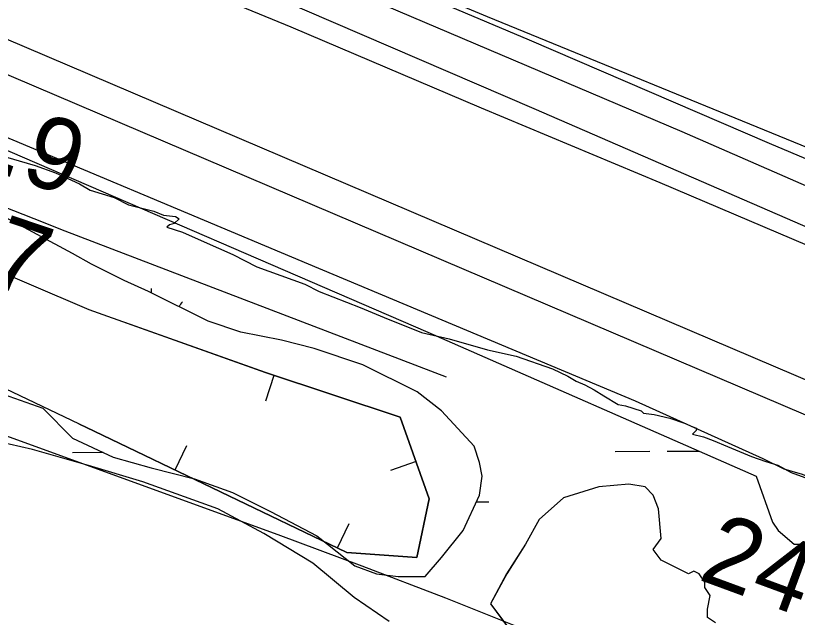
# Model space of a CAD drawing. Extents: x 3329297 to 3367176, y 649250 to 674653.
# Drawn here: x 3337023 to 3337745, y 671007 to 671563 of the extents above; entities that cross this region are included whole.
import ezdxf

# ---------------------------------------------------------------- set-up
doc = ezdxf.new("R2010")
doc.units = 0
for name, color, linetype in [('V-BORW-LINE', 7, 'Continuous'), ('V-LEVE-TOET', 7, 'Continuous'), ('V-RIVR-EDGE', 7, 'Continuous'), ('V-RIVR-RANG', 7, 'Continuous'), ('V-ROAD-CNTR', 7, 'Continuous'), ('V-SITE-VEGE', 7, 'Continuous'), ('V-SURV-LINE', 7, 'Continuous'), ('V-TOPO-MAJR', 7, 'Continuous'), ('V-TOPO-SHOR', 7, 'Continuous'), ('V-WETL-SWMP', 7, 'Continuous')]:
    doc.layers.add(name, color=color, linetype=linetype)

msp = doc.modelspace()

# ---------------------------------------------------------------- linework, layer by layer
at = {"layer": 'V-BORW-LINE'}
for p, q in [((3337261.34, 671230.61), (3337253.51, 671206.87)), ((3337169.91, 671143.17), (3337180.72, 671165.71)), ((3337392.71, 671150.96), (3337369.16, 671142.59)), ((3337320.11, 671071.1), (3337330.93, 671093.64))]:
    msp.add_line(p, q, dxfattribs=at)
for points in [[(3336137.13, 671704.9), (3336329.71, 671609.64), (3336446.55, 671579.02), (3336516.76, 671528.05), (3336660.06, 671480.86), (3336870.09, 671385.28), (3337090.13, 671291.42), (3337253.57, 671233.18), (3337378.09, 671192.1), (3337404.91, 671116.64), (3337393.5, 671062.16), (3337328.83, 671066.91), (3337095.24, 671179), (3336875.94, 671283.56), (3336663.33, 671355.4), (3336502.56, 671407.46), (3336272.56, 671492.78), (3336062.54, 671602.07)], [(3337080.86, 671185.86), (3337095.24, 671179), (3337328.83, 671066.91), (3337393.5, 671062.16), (3337404.91, 671116.64), (3337378.09, 671192.1), (3337253.57, 671233.18), (3337123.46, 671279.54)]]:
    msp.add_lwpolyline(points, dxfattribs=at)
at = {"layer": 'V-LEVE-TOET'}
for points in [[(3335803.12, 672183.55), (3335980.51, 672109.48), (3336073.36, 672067.84), (3336217.76, 672005.99), (3336352.53, 671946.93), (3336517.19, 671873.95), (3336710.98, 671786.23), (3336942.43, 671688.86), (3337134.25, 671611.38), (3337276.94, 671552.63), (3337452.78, 671477.7), (3337618.08, 671408.71), (3337810.05, 671327.27)], [(3340086.07, 669878.32), (3339928.04, 670005.5), (3339884.34, 670048.24), (3339817.4, 670097.22), (3339686.01, 670171.48), (3339507.75, 670267.73), (3339342.66, 670351.8), (3339186.35, 670434.62), (3338995.14, 670537.52), (3338794.67, 670646.24), (3338482.64, 670816.66), (3338239.58, 670927.07), (3338016.97, 671021.61), (3337749.83, 671139.03), (3337732.98, 671143.93), (3337713.57, 671153.49), (3337595.68, 671206.86), (3337293.29, 671333.23), (3336964.27, 671471.26), (3336549.79, 671644.86), (3336202.79, 671796.48), (3335798.63, 671978.49)]]:
    msp.add_lwpolyline(points, dxfattribs=at)
at = {"layer": 'V-RIVR-EDGE'}
msp.add_spline([(3339166.35, 669632.45), (3339148.52, 669636.37), (3339138.83, 669636.78), (3339122.94, 669641.48), (3339105.12, 669646.95), (3339096.99, 669652.01), (3339093.12, 669656.29), (3339089.26, 669664.44), (3339086.56, 669669.1), (3339078.82, 669674.94), (3339053.64, 669688.18), (3339028.47, 669702.21), (3339020.72, 669706.49), (3339018, 669704.17), (3339012.57, 669704.57), (3339008.7, 669708.07), (3339008.32, 669710.4), (3339007.94, 669713.12), (3339007.56, 669715.06), (3338988.58, 669723.63), (3338974.64, 669732.59), (3338973.09, 669734.53), (3338972.71, 669738.02), (3338974.27, 669740.35), (3338974.28, 669743.84), (3338966.94, 669753.94), (3338965.01, 669758.6), (3338963.85, 669760.54), (3338956.49, 669764.43), (3338944.87, 669769.5), (3338928.21, 669778.08), (3338920.86, 669785.07), (3338906.56, 669803.34), (3338897.28, 669814.22), (3338888, 669824.71), (3338880.26, 669833.26), (3338874.07, 669838.71), (3338867.87, 669840.27), (3338862.06, 669843), (3338858.57, 669843.01), (3338858.58, 669844.95), (3338858.24, 669867.83), (3338860.58, 669870.93), (3338861.75, 669873.25), (3338861.76, 669876.35), (3338860.21, 669879.46), (3338854.02, 669882.58), (3338849.02, 669903.14), (3338843.63, 669917.51), (3338832.81, 669931.11), (3338822.75, 669940.83), (3338804.56, 669955.22), (3338800.68, 669956.78), (3338796.03, 669956.79), (3338788.66, 669955.26), (3338782.44, 669952.17), (3338775.47, 669955.68), (3338770.44, 669960.35), (3338765.41, 669965.01), (3338754.18, 669972.41), (3338742.57, 669981.36), (3338728.24, 669988.76), (3338714.68, 669995), (3338701.13, 670003.56), (3338693.4, 670012.11), (3338687.99, 670020.27), (3338682.59, 670033.47), (3338677.18, 670040.46), (3338665.17, 670046.31), (3338655.1, 670048.66), (3338655.48, 670045.95), (3338653.54, 670045.56), (3338643.46, 670046.36), (3338635.32, 670050.26), (3338633, 670052.98), (3338626.41, 670055.33), (3338615.17, 670057.29), (3338608.97, 670058.08), (3338601.61, 670062.76), (3338592.32, 670069.37), (3338582.25, 670071.72), (3338574.11, 670074.46), (3338568.3, 670078.74), (3338562.5, 670084.57), (3338561.34, 670087.67), (3338554.75, 670088.85), (3338551.26, 670089.25), (3338548.94, 670091.97), (3338544.31, 670098.58), (3338517.19, 670108.73), (3338513.32, 670111.84), (3338511.39, 670115.72), (3338497.82, 670118.86), (3338480, 670125.88), (3338471.48, 670130.17), (3338466.45, 670134.83), (3338451.73, 670140.3), (3338441.26, 670142.65), (3338438.16, 670142.27), (3338431.18, 670145.39), (3338420.34, 670150.07), (3338407.93, 670152.43), (3338393.21, 670156.73), (3338378.49, 670165.69), (3338345.2, 670189.43), (3338316.55, 670206.56), (3338280.93, 670231.47), (3338237.55, 670254.45), (3338210.45, 670270.81), (3338182.57, 670289.88), (3338148.9, 670317.5), (3338126.07, 670336.94), (3338116.01, 670348.22), (3338106.73, 670356.77), (3338093.56, 670363.78), (3338076.9, 670368.87), (3338057.53, 670376.28), (3338042.81, 670383.3), (3338026.54, 670392.65), (3338007.18, 670402.39), (3337994, 670405.52), (3337971.52, 670413.34), (3337948.66, 670420.76), (3337916.51, 670434.03), (3337912.65, 670440.63), (3337911.11, 670448.78), (3337908.8, 670453.82), (3337904.54, 670455.77), (3337890.98, 670459.68), (3337883.62, 670464.74), (3337879.36, 670466.69), (3337872.38, 670467.1), (3337862.68, 670467.12), (3337849.88, 670465.99), (3337839.8, 670463.69), (3337826.22, 670462.56), (3337810.72, 670465.7), (3337802.19, 670469.21), (3337788.25, 670478.16), (3337779.73, 670480.51), (3337774.3, 670481.69), (3337768.89, 670486.74), (3337764.63, 670490.63), (3337755.72, 670494.92), (3337749.13, 670496.88), (3337745.26, 670497.27), (3337740.6, 670495.35), (3337738.66, 670496.13), (3337735.18, 670499.24), (3337729.76, 670503.52), (3337724.73, 670508.18), (3337720.08, 670512.07), (3337706.13, 670514.43), (3337677.86, 670531.18), (3337643.77, 670545.22), (3337600.78, 670567.05), (3337560.1, 670585.37), (3337510.14, 670611.87), (3337463.28, 670636.42), (3337442.36, 670644.22), (3337416.78, 670652.43), (3337405.55, 670657.5), (3337401.68, 670661.39), (3337400.13, 670663.33), (3337395.49, 670665.67), (3337388.89, 670666.07), (3337376.88, 670670.76), (3337362.94, 670677.77), (3337340.87, 670690.62), (3337309.5, 670706.99), (3337291.29, 670714.79), (3337276.18, 670722.97), (3337252.56, 670736.99), (3337220.04, 670756.85), (3337154.99, 670798.5), (3337124.41, 670821.07), (3337111.24, 670827.31), (3337094.19, 670832.78), (3337075.97, 670836.7), (3337050.39, 670842.59), (3337028.69, 670849.62), (3337007.78, 670860.53), (3336991.89, 670867.94), (3336983.37, 670871.06), (3336969.03, 670873.42), (3336939.95, 670875.43), (3336901.97, 670884.45), (3336863.6, 670895.79), (3336821.37, 670910.63), (3336786.5, 670926.23), (3336740.02, 670949.61), (3336682.31, 670976.12), (3336635.44, 670997.18), (3336603.68, 671013.55), (3336585.47, 671022.51), (3336583.15, 671026.4), (3336580.06, 671031.06), (3336576.19, 671034.56), (3336549.46, 671045.09), (3336500.24, 671058.01), (3336451.41, 671070.16), (3336425.44, 671074.49), (3336399.85, 671076.49), (3336361.07, 671078.91), (3336337.43, 671082.85), (3336313.4, 671088.34), (3336290.92, 671094.6), (3336280.46, 671097.34), (3336275.41, 671097.35), (3336257.58, 671097.39), (3336194.82, 671123.92), (3336129.35, 671154.33), (3336078.61, 671179.66), (3336032.91, 671203.04), (3335979.46, 671230.32), (3335943.05, 671245.54), (3335907.79, 671259.2), (3335894.23, 671264.66), (3335887.64, 671265.45), (3335873.31, 671273.63), (3335871.38, 671277.13), (3335862.86, 671281.41), (3335831.09, 671293.51), (3335799.33, 671308.72), (3335763.7, 671327.42), (3335724.58, 671346.9), (3335714.51, 671351.97), (3335703.27, 671355.1), (3335699.01, 671358.21), (3335680.04, 671369.9), (3335645.95, 671385.49), (3335603.71, 671399.17), (3335573.09, 671406.61), (3335518.06, 671419.93), (3335470.4, 671436.73), (3335433.98, 671449.62), (3335405.32, 671465.97), (3335397.96, 671471.03), (3335385.94, 671471.06), (3335366.94, 671468.78), (3335345.98, 671463.02), (3335338.62, 671464.59), (3335338.62, 671467.3), (3335339.03, 671475.83), (3335337.87, 671478.94), (3335334.39, 671482.05), (3335319.67, 671486.74), (3335303, 671491.05), (3335280.12, 671488.39), (3335259.15, 671479.52), (3335245.56, 671472.19), (3335233.15, 671471.44), (3335223.85, 671474.18), (3335210.68, 671481.97), (3335198.67, 671485.88), (3335156.4, 671487.53), (3335124.61, 671488.39), (3335114.13, 671484.92), (3335094.71, 671474.11), (3335085.4, 671473.36), (3335075.32, 671475.71), (3335065.63, 671477.67), (3335064.86, 671478.45), (3335067.59, 671483.1), (3335066.81, 671484.65), (3335063.72, 671489.31), (3335039.71, 671501.39), (3335020.73, 671509.2), (3335003.28, 671511.95), (3334994.76, 671515.46), (3334990.89, 671517.03), (3334963, 671533.38), (3334933.18, 671549.36), (3334916.12, 671551.34), (3334894.42, 671557.6), (3334863.43, 671571.25), (3334847.95, 671581.75), (3334834.78, 671587.99), (3334809.21, 671598.53), (3334767.76, 671617.24), (3334744.9, 671627.77), (3334711.2, 671642.2), (3334691.44, 671649.23), (3334670.12, 671653.16), (3334647.65, 671659.81), (3334620.14, 671672.29), (3334605.42, 671678.53), (3334581, 671683.24), (3334555.81, 671689.12), (3334542.23, 671688.38), (3334534.09, 671688.79), (3334531.39, 671696.55), (3334523.66, 671706.27), (3334505.85, 671714.84), (3334480.26, 671719.17), (3334460.49, 671721.93), (3334457, 671720.39), (3334455.05, 671716.91), (3334456.59, 671713.8), (3334463.19, 671714.56), (3334467.45, 671712.22), (3334467.44, 671710.28), (3334462.78, 671708.35), (3334446.88, 671706.84), (3334429.04, 671707.66), (3334403.46, 671713.93), (3334397.66, 671718.6), (3334391.46, 671722.88), (3334378.67, 671723.69), (3334340.28, 671727.27), (3334305.39, 671730.07), (3334290.26, 671730.11), (3334281.35, 671731.68), (3334271.66, 671734.81), (3334266.23, 671735.6), (3334258.08, 671732.9), (3334246.43, 671726.73), (3334241.39, 671726.35), (3334232.48, 671729.48), (3334218.91, 671729.9), (3334190.6, 671730.74), (3334178.97, 671731.94), (3334163.47, 671737.4), (3334156.1, 671736.65), (3334151.44, 671732.39), (3334148.33, 671732.4), (3334142.53, 671735.91), (3334132.83, 671736.32), (3334110.73, 671737.53), (3334106.86, 671739.48), (3334099.89, 671744.15), (3334081.28, 671748.08), (3334072.75, 671747.71), (3334041.74, 671753.61), (3334018.09, 671757.54), (3334010.35, 671760.28), (3333999.89, 671767.67), (3333992.15, 671771.95), (3333987.1, 671771.19), (3333984.38, 671768.48), (3333980.12, 671768.49), (3333976.64, 671772.77), (3333969.66, 671775.11), (3333958.81, 671778.24), (3333949.91, 671783.31), (3333945.64, 671782.93), (3333941.37, 671782.16), (3333931.3, 671788.01), (3333925.87, 671788.02), (3333915.4, 671788.82), (3333900.29, 671791.57), (3333878.2, 671798.61), (3333856.9, 671811.07), (3333845.68, 671822.73), (3333832.9, 671828.97), (3333818.18, 671834.82), (3333817.41, 671837.15), (3333813.53, 671837.55), (3333800.36, 671841.85), (3333795.71, 671844.96), (3333793.79, 671851.56), (3333792.24, 671854.28), (3333782.95, 671858.18), (3333767.85, 671869.46), (3333755.47, 671879.57), (3333746.17, 671884.64), (3333742.68, 671886.2), (3333733.76, 671885.83), (3333720.97, 671886.64), (3333714.38, 671889.76), (3333707.8, 671895.2), (3333701.62, 671902.59), (3333696.98, 671908.42), (3333690.4, 671913.09), (3333677.23, 671920.49), (3333664.47, 671934.87), (3333650.92, 671945.76), (3333635.04, 671952), (3333625.75, 671959.78), (3333617.63, 671968.72), (3333606.39, 671969.91), (3333600.97, 671974.19), (3333597.87, 671978.08), (3333590.14, 671988.96), (3333572.36, 672009.16), (3333553.4, 672029.38), (3333532.11, 672045.72), (3333511.21, 672062.06), (3333486.44, 672080.35), (3333466.3, 672090.87), (3333451.59, 672102.92), (3333445.79, 672109.53), (3333446.58, 672114.96), (3333429.16, 672126.25), (3333421.43, 672137.9), (3333420.68, 672148.76), (3333415.26, 672151.1), (3333404.71, 672151.61)], degree=3, dxfattribs=at)
at = {"layer": 'V-ROAD-CNTR'}
msp.add_lwpolyline([(3333809.31, 672820), (3333944.42, 672747.26), (3334258.78, 672580.23), (3334296.17, 672566.76), (3334344.19, 672549.65), (3334408.2, 672530.54), (3334613.43, 672493.6), (3334989.87, 672438.82), (3335297.58, 672391.89), (3335424.13, 672366.25), (3335501.55, 672349.66), (3335549.88, 672333.02), (3335599.75, 672320.68), (3335802.21, 672231.62), (3336229.96, 672053.99), (3336981.64, 671735.07), (3337638.29, 671456.08), (3338236.55, 671194.84)], dxfattribs=at)
at = {"layer": 'V-SITE-VEGE'}
for p, q in [((3337458.65, 671562.05), (3337114.11, 671706.29)), ((3337755.37, 671440.62), (3337458.65, 671562.05)), ((3337000.47, 671436.23), (3337040.46, 671424.65)), ((3337040.46, 671424.65), (3337059.33, 671417.76)), ((3337059.33, 671417.76), (3337081.51, 671407.49)), ((3337081.51, 671407.49), (3337091.48, 671401.81)), ((3337091.48, 671401.81), (3337113.69, 671394.89)), ((3337113.69, 671394.89), (3337126.98, 671388.06)), ((3337126.98, 671388.06), (3337150.32, 671382.23)), ((3337075.17, 671343.37), (3336999.92, 671383.54)), ((3337150.32, 671382.23), (3337159.2, 671378.79)), ((3337159.2, 671378.79), (3337170.33, 671377.56)), ((3337173.65, 671375.29), (3337169.14, 671370.88)), ((3337170.33, 671377.56), (3337173.65, 671375.29)), ((3337164.67, 671369.82), (3337162.42, 671367.61)), ((3337162.42, 671367.61), (3337176.86, 671363)), ((3337169.14, 671370.88), (3337164.67, 671369.82)), ((3337176.86, 671363), (3337196.82, 671353.86)), ((3337196.82, 671353.86), (3337223.44, 671342.43)), ((3337092.73, 671333.33), (3337075.17, 671343.37)), ((3337223.44, 671342.43), (3337245.6, 671331.05)), ((3337122.83, 671318.27), (3337092.73, 671333.33)), ((3337245.6, 671331.05), (3337290, 671314.96)), ((3337145.4, 671308.23), (3337122.83, 671318.27)), ((3337200.58, 671280.61), (3337145.4, 671308.23)), ((3337290, 671314.96), (3337303.3, 671308.13)), ((3337303.3, 671308.13), (3337341.02, 671293.24)), ((3337341.02, 671293.24), (3337363.21, 671284.08)), ((3337230.68, 671270.57), (3337200.58, 671280.61)), ((3337363.21, 671284.08), (3337397.61, 671270.34)), ((3337268.31, 671263.04), (3337230.68, 671270.57)), ((3337397.61, 671270.34), (3337423.18, 671264.48)), ((3337298.41, 671255.51), (3337268.31, 671263.04)), ((3337423.18, 671264.48), (3337458.72, 671254.07)), ((3337343.56, 671240.45), (3337298.41, 671255.51)), ((3337458.72, 671254.07), (3337485.4, 671248.21)), ((3337485.4, 671248.21), (3337518.71, 671236.7)), ((3337393.72, 671215.35), (3337343.56, 671240.45)), ((3337518.71, 671236.7), (3337533.12, 671229.86)), ((3337533.12, 671229.86), (3337540.87, 671225.32)), ((3337540.87, 671225.32), (3337548.63, 671221.89)), ((3337548.63, 671221.89), (3337557.5, 671217.34)), ((3337004.94, 671215.35), (3337047.58, 671200.28)), ((3337416.3, 671197.78), (3337393.72, 671215.35)), ((3337557.5, 671217.34), (3337566.35, 671211.67)), ((3337566.35, 671211.67), (3337579.64, 671203.72)), ((3337047.58, 671200.28), (3337075.17, 671172.67)), ((3337579.64, 671203.72), (3337586.31, 671202.54)), ((3337586.31, 671202.54), (3337600.75, 671197.92)), ((3337446.4, 671165.14), (3337416.3, 671197.78)), ((3337600.75, 671197.92), (3337602.95, 671195.67)), ((3337602.95, 671195.67), (3337612.97, 671194.45)), ((3337612.97, 671194.45), (3337627.42, 671190.95)), ((3337627.42, 671190.95), (3337640.74, 671186.35)), ((3337640.74, 671186.35), (3337648.5, 671182.92)), ((3337651.81, 671179.54), (3337648.43, 671176.23)), ((3337648.5, 671182.92), (3337651.83, 671181.77)), ((3337651.83, 671181.77), (3337651.81, 671179.54)), ((3337075.17, 671172.67), (3337112.79, 671155.1)), ((3337648.43, 671176.23), (3337658.43, 671173.9)), ((3337658.43, 671173.9), (3337667.31, 671170.45)), ((3337451.42, 671150.08), (3337446.4, 671165.14)), ((3337667.31, 671170.45), (3337680.62, 671164.74)), ((3337680.62, 671164.74), (3337702.81, 671155.58)), ((3337112.79, 671155.1), (3337147.91, 671145.06)), ((3337453.92, 671137.53), (3337451.42, 671150.08)), ((3337702.81, 671155.58), (3337716.13, 671150.98)), ((3337716.13, 671150.98), (3337727.23, 671147.52)), ((3337147.91, 671145.06), (3337188.04, 671135.02)), ((3337727.23, 671147.52), (3337739.42, 671140.7)), ((3337188.04, 671135.02), (3337223.16, 671122.47)), ((3337451.42, 671119.95), (3337453.92, 671137.53)), ((3337739.42, 671140.7), (3337771.61, 671129.21)), ((3337589.37, 671129.99), (3337561.78, 671127.48)), ((3337604.42, 671127.48), (3337589.37, 671129.99)), ((3337223.16, 671122.47), (3337258.27, 671104.89)), ((3337561.78, 671127.48), (3337529.17, 671117.44)), ((3337611.95, 671119.95), (3337604.42, 671127.48)), ((3337436.36, 671087.32), (3337451.42, 671119.95)), ((3337529.17, 671117.44), (3337506.6, 671097.36)), ((3337616.96, 671107.4), (3337611.95, 671119.95)), ((3337619.47, 671079.79), (3337616.96, 671107.4)), ((3337258.27, 671104.89), (3337300.92, 671082.3)), ((3337506.6, 671097.36), (3337494.05, 671074.77)), ((3337416.3, 671062.22), (3337436.36, 671087.32)), ((3337300.92, 671082.3), (3337310.95, 671074.77)), ((3337611.95, 671069.75), (3337619.47, 671079.79)), ((3337310.95, 671074.77), (3337336.03, 671054.69)), ((3337494.05, 671074.77), (3337476.49, 671047.16)), ((3337619.47, 671059.7), (3337611.95, 671069.75)), ((3337401.25, 671044.65), (3337416.3, 671062.22)), ((3337644.55, 671047.16), (3337619.47, 671059.7)), ((3337336.03, 671054.69), (3337356.1, 671047.16)), ((3337649.57, 671049.66), (3337644.55, 671047.16)), ((3337654.59, 671047.16), (3337649.57, 671049.66)), ((3337356.1, 671047.16), (3337376.17, 671044.65)), ((3337376.17, 671044.65), (3337401.25, 671044.65)), ((3337476.49, 671047.16), (3337461.45, 671019.54)), ((3337659.6, 671039.62), (3337654.59, 671047.16)), ((3337659.6, 671034.6), (3337659.6, 671039.62)), ((3337664.62, 671027.07), (3337659.6, 671034.6)), ((3337662.11, 671014.52), (3337664.62, 671027.07)), ((3337461.45, 671019.54), (3337476.49, 670999.46)), ((3337662.11, 671006.99), (3337662.11, 671014.52))]:
    msp.add_line(p, q, dxfattribs=at)
at = {"layer": 'V-SURV-LINE'}
for points in [[(3335488.59, 672191.71), (3338475.92, 670918.34)], [(3338464.18, 670890.74), (3335476.85, 672164.11)]]:
    msp.add_lwpolyline(points, dxfattribs=at)
at = {"layer": 'V-TOPO-MAJR'}
for points in [[(3336063.42, 671555), (3336909.83, 671212.05), (3336928.81, 671205.31), (3336947.77, 671198.54), (3336966.71, 671191.73), (3336985.64, 671184.88), (3337264.9, 671083.52), (3337342.56, 671054.68), (3337419.92, 671025.06), (3337496.83, 670994.29), (3337573.43, 670962.74), (3337673.72, 670920.57), (3337699.91, 670909.43), (3337726.05, 670898.17), (3337752.09, 670886.69)], [(3337420.81, 671228.93), (3337068.44, 671363.98), (3337039.57, 671375.21), (3337010.78, 671386.64), (3336982.1, 671398.35), (3336953.49, 671410.26), (3336770.84, 671487.36), (3336766.73, 671491.69), (3336764.9, 671496.08), (3336766.5, 671500.55), (3336770.39, 671505.08), (3336789.75, 671514.44)]]:
    msp.add_lwpolyline(points, dxfattribs=at)
at = {"layer": 'V-TOPO-SHOR'}
for points in [[(3339142.68, 670711.72), (3338975.73, 670800.12), (3338657.82, 670969.84), (3338506.87, 671044.08), (3338419.85, 671084.72), (3338229.85, 671167.75), (3337750.42, 671369.11), (3337501.82, 671476.87), (3337075.65, 671660.59), (3336796.87, 671778.93), (3336706.31, 671817.8), (3336182.49, 672038.59), (3335965.85, 672133.99), (3335663.98, 672262.94), (3335582.31, 672294.72), (3335532.6, 672310.59), (3335477.57, 672324.68), (3335422.55, 672335.23), (3335149.23, 672380.84), (3334615.03, 672457.9), (3334494.34, 672478.96)], [(3336581.02, 671929.34), (3336911.29, 671788.02), (3337497.26, 671540.73), (3337719.23, 671445.34), (3338024.64, 671316.4), (3338243.05, 671222.78), (3338449.03, 671136.23), (3338537.82, 671092.04), (3338731.41, 670993.05), (3339100.82, 670796.8), (3339280.2, 670699.56), (3339711.78, 670471.5), (3339889.39, 670374.25), (3340001.3, 670303.49), (3340054.6, 670266.33), (3340090.14, 670238.01), (3340107.9, 670227.4), (3340141.62, 670223.91), (3340193.06, 670229.33), (3340217.87, 670245.35), (3340235.58, 670263.12), (3340379.09, 670368.08)]]:
    msp.add_lwpolyline(points, dxfattribs=at)
at = {"layer": 'V-WETL-SWMP'}
for p, q in [((3336746.58, 671554.24), (3337403.76, 671270.58)), ((3337075.17, 671343.37), (3336999.92, 671383.54)), ((3337092.73, 671333.33), (3337075.17, 671343.37)), ((3337122.83, 671318.27), (3337092.73, 671333.33)), ((3337145.4, 671308.23), (3337122.83, 671318.27)), ((3337200.58, 671280.61), (3337145.4, 671308.23)), ((3337148.13, 671306.86), (3337148.13, 671311.01)), ((3337230.68, 671270.57), (3337200.58, 671280.61)), ((3337268.31, 671263.04), (3337230.68, 671270.57)), ((3337403.76, 671270.58), (3337707.26, 671137.53)), ((3337298.41, 671255.51), (3337268.31, 671263.04)), ((3337343.56, 671240.45), (3337298.41, 671255.51)), ((3337393.72, 671215.35), (3337343.56, 671240.45)), ((3337004.94, 671215.35), (3337047.58, 671200.28)), ((3337416.3, 671197.77), (3337393.72, 671215.35)), ((3337047.58, 671200.28), (3337075.17, 671172.67)), ((3337446.4, 671165.14), (3337416.3, 671197.77)), ((3337038.15, 671162), (3336947.58, 671182.91)), ((3337075.17, 671172.67), (3337112.79, 671155.1)), ((3337451.41, 671150.08), (3337446.4, 671165.14)), ((3337089.88, 671147.46), (3337038.15, 671162)), ((3337075, 671159.44), (3337103.38, 671159.5)), ((3337576.91, 671160.39), (3337608.91, 671160.45)), ((3337624.91, 671160.48), (3337654.77, 671160.54)), ((3337112.79, 671155.1), (3337147.91, 671145.06)), ((3337453.92, 671137.53), (3337451.41, 671150.08)), ((3337140.08, 671132.08), (3337089.88, 671147.46)), ((3337147.91, 671145.06), (3337188.04, 671135.02)), ((3337188.04, 671135.02), (3337223.16, 671122.47)), ((3337451.41, 671119.96), (3337453.92, 671137.53)), ((3337707.26, 671137.53), (3337722.31, 671094.86)), ((3337209.54, 671107.2), (3337140.08, 671132.08)), ((3337589.37, 671129.99), (3337561.78, 671127.48)), ((3337604.42, 671127.48), (3337589.37, 671129.99)), ((3337223.16, 671122.47), (3337258.27, 671104.89)), ((3337561.78, 671127.48), (3337529.17, 671117.44)), ((3337611.95, 671119.95), (3337604.42, 671127.48)), ((3337436.36, 671087.32), (3337451.41, 671119.96)), ((3337448.54, 671113.72), (3337459.94, 671113.74)), ((3337529.17, 671117.44), (3337506.6, 671097.36)), ((3337616.96, 671107.4), (3337611.95, 671119.95)), ((3337252.14, 671084.44), (3337209.54, 671107.2)), ((3337619.47, 671079.79), (3337616.96, 671107.4)), ((3337258.27, 671104.89), (3337300.92, 671082.3)), ((3337506.6, 671097.36), (3337494.05, 671074.77)), ((3337722.31, 671094.86), (3337727.33, 671087.33)), ((3337297.29, 671057.05), (3337252.14, 671084.44)), ((3337416.3, 671062.22), (3337436.36, 671087.32)), ((3337727.33, 671087.33), (3337742.38, 671074.77)), ((3337300.92, 671082.3), (3337310.95, 671074.77)), ((3337611.95, 671069.75), (3337619.47, 671079.79)), ((3337310.95, 671074.77), (3337336.03, 671054.69)), ((3337494.05, 671074.77), (3337476.5, 671047.15)), ((3337619.47, 671059.71), (3337611.95, 671069.75)), ((3337742.38, 671074.77), (3337754.92, 671074.77)), ((3337335.52, 671025.46), (3337297.29, 671057.05)), ((3337401.25, 671044.65), (3337416.3, 671062.22)), ((3337644.55, 671047.15), (3337619.47, 671059.71)), ((3337336.03, 671054.69), (3337356.1, 671047.16)), ((3337649.57, 671049.66), (3337644.55, 671047.15)), ((3337654.59, 671047.15), (3337649.57, 671049.66)), ((3337356.1, 671047.16), (3337376.17, 671044.65)), ((3337376.17, 671044.65), (3337401.25, 671044.65)), ((3337476.5, 671047.15), (3337461.45, 671019.54)), ((3337659.6, 671039.62), (3337654.59, 671047.15)), ((3337659.6, 671034.6), (3337659.6, 671039.62)), ((3337664.62, 671027.07), (3337659.6, 671034.6)), ((3337662.11, 671014.52), (3337664.62, 671027.07)), ((3337367.87, 671003.09), (3337335.52, 671025.46)), ((3337461.45, 671019.54), (3337476.5, 670999.46)), ((3337662.11, 671006.99), (3337662.11, 671014.52)), ((3337669.64, 671001.97), (3337662.11, 671006.99))]:
    msp.add_line(p, q, dxfattribs=at)
msp.add_arc((3337203.44, 671275.59), 35.25, 139.33648, 148.18559, dxfattribs=at)

# ---------------------------------------------------------------- texts
at = {"layer": 'V-RIVR-RANG'}
for s, rotation, p in [('29.9', 341.34833, (3336906.82, 671451.23)), ('24.7', 341.34833, (3336875.32, 671356.31)), ('24.4', 339.80833, (3337652.28, 671042.44))]:
    msp.add_text(s, height=67, rotation=rotation, dxfattribs=at).set_placement(p)

doc.saveas('drawing.dxf')
